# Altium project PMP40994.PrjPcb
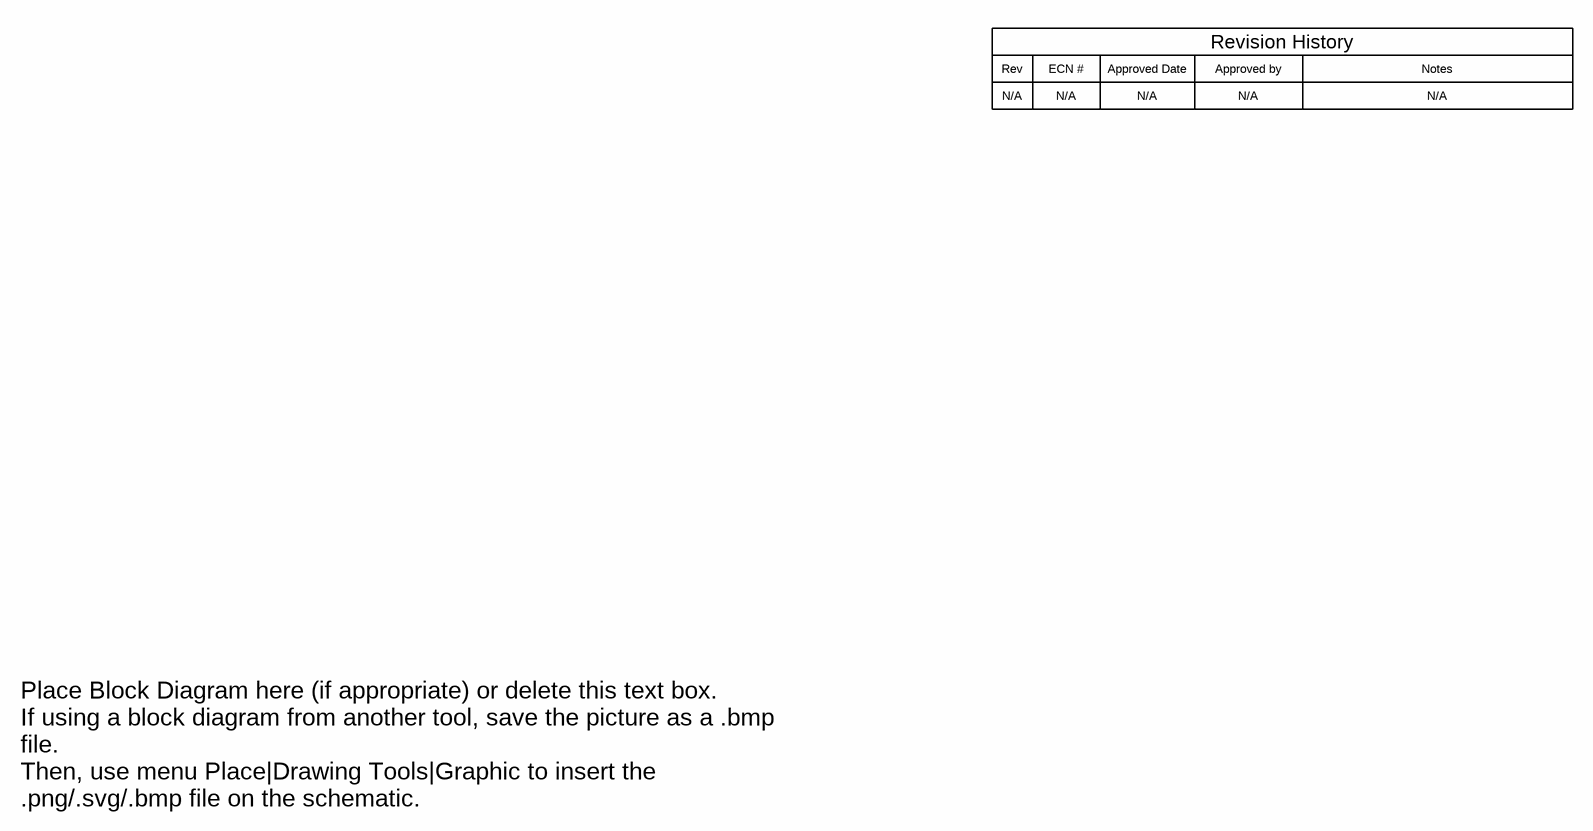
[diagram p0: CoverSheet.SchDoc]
CopyrightYear: 2022; EVM_Orderable: N/A; PCB_Layout: Max Wang; PCB_Rev: E1; PRJ_Customer: Public Release; PRJ_Engineer: Max Wang; PRJ_Number: PMP40994; PRJ_Title: Isolated Bias power and Gate Driver daughter board; SCH_Rev: E1; TechSupport: http://www.ti.com/support; TID: PMP40994
3 sheets, 65 parts. Net scope: global (net labels, ports and power ports of the same name join across sheets).
Board file: PMP40994.PcbDoc
Sheets:
  CoverSheet.SchDoc
  Driver Daughter board.SchDoc
  Hardware.SchDoc

## Sheet CoverSheet.SchDoc
size 431 x 279 mm; Date: Not shown in title block; ApprovedBy: Not shown in title block; CheckedBy: Not shown in title block; Author: Not shown in title block; CompanyName: Not shown in title block; Engineer: Not shown in title block; Organization: Not shown in title block; Address1: Not shown in title block; Address2: Not shown in title block; Address3: Not shown in title block; Address4: Not shown in title block; DocumentNumber: 1; Revision: Use project parameter SCH_Rev; SheetNumber: 1; SheetTotal: 3; PageSetup: Record=PageOptions¦CenterHorizontal=True¦CenterVertical=True¦PrintScale=1.00¦XCorrection=1.00¦YCorrection=1.00¦PrintKind=0¦BorderSize=5000000¦LeftOffset=0¦BottomOffset=0¦Orientation=2¦PaperLength=1000¦PaperWidth=1000¦Scale=100¦PaperSource=15¦PrintQuality=600¦MediaType=1¦DitherType=10¦PaperKind=Letter¦PrintScaleMode=1

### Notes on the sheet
- Rev
- N/A
- ECN #
- Approved Date
- Approved by
- Revision History
- Notes
- Place Block Diagram here (if appropriate) or delete this text box.
  If using a block diagram from another tool, save the picture as a .bmp file.
  Then, use menu Place|Drawing Tools|Graphic to insert the .png/.svg/.bmp file on the schematic.

## Sheet Driver Daughter board.SchDoc
size 431 x 279 mm; Date: Not shown in title block; ApprovedBy: Not shown in title block; CheckedBy: Not shown in title block; Author: Not shown in title block; CompanyName: Not shown in title block; Engineer: Not shown in title block; Organization: Not shown in title block; Address1: Not shown in title block; Address2: Not shown in title block; Address3: Not shown in title block; Address4: Not shown in title block; DocumentNumber: 1; Revision: Use project parameter SCH_Rev; SheetNumber: 1; SheetTotal: 3; PageSetup: Record=PageOptions¦CenterHorizontal=True¦CenterVertical=True¦PrintScale=1.00¦XCorrection=1.00¦YCorrection=1.00¦PrintKind=0¦BorderSize=5000000¦LeftOffset=0¦BottomOffset=0¦Orientation=2¦PaperLength=1000¦PaperWidth=1000¦Scale=100¦PaperSource=15¦PrintQuality=600¦MediaType=1¦DitherType=10¦PaperKind=Letter¦PrintScaleMode=1
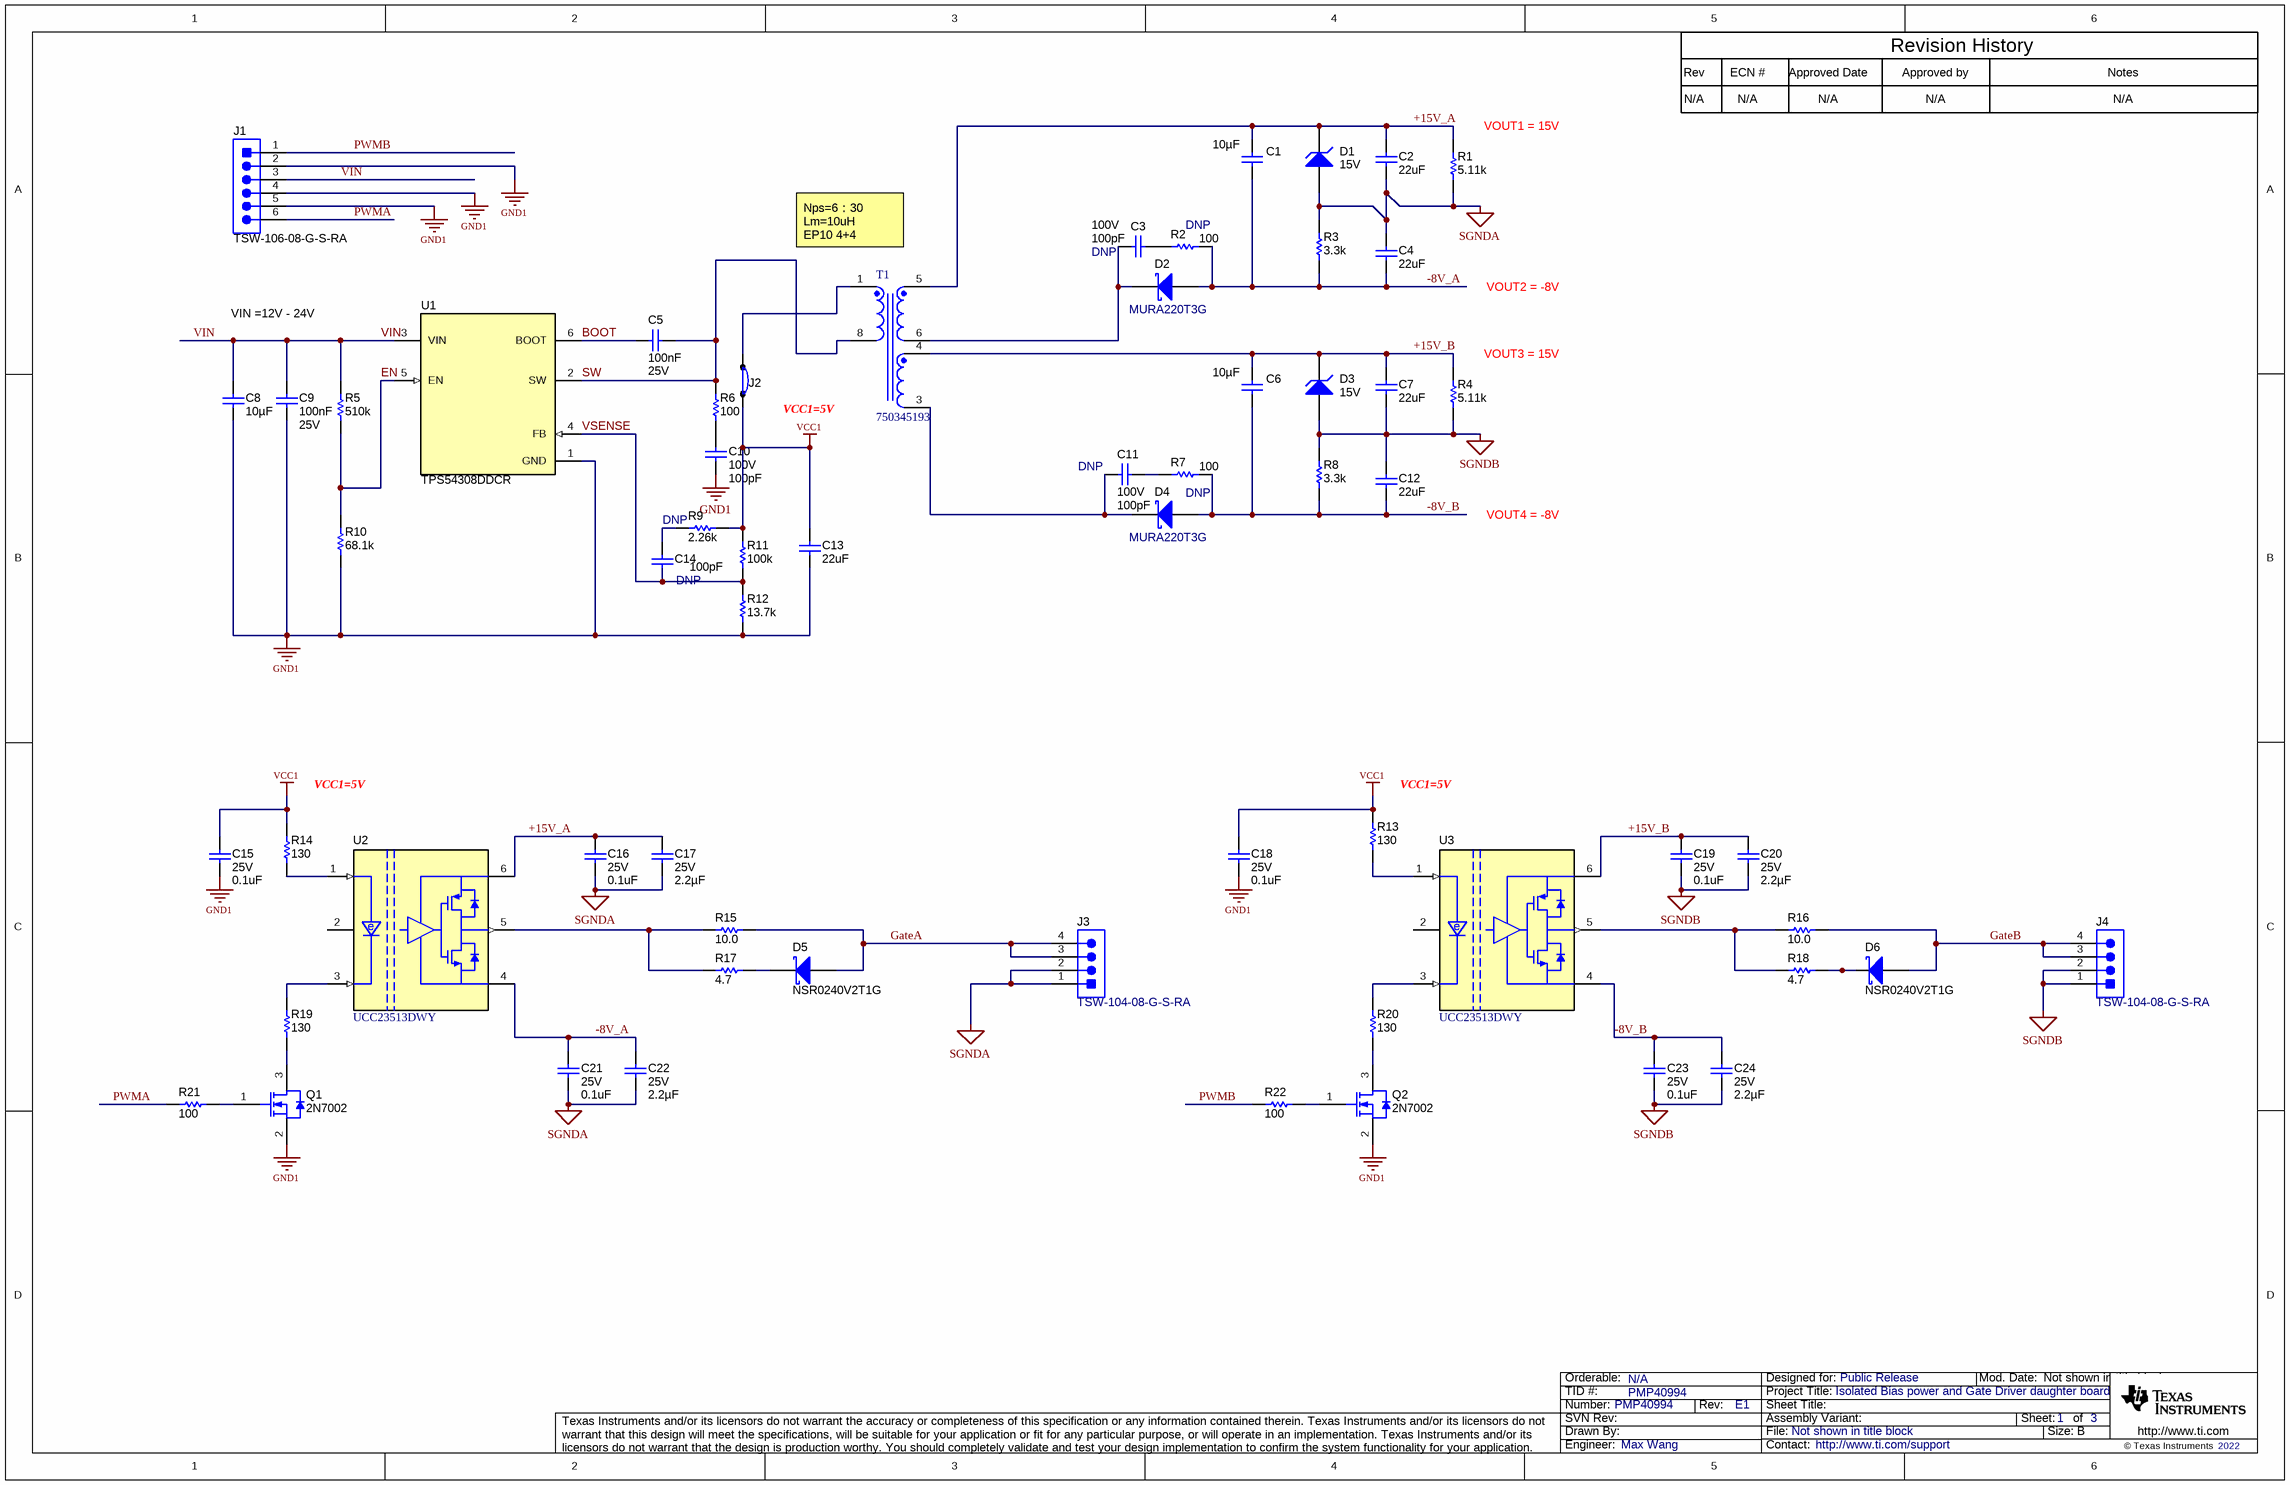
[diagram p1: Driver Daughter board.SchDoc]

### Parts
C1  ValueDisplayed: 10µF  [1210_280]  (hidden comment: C3225X7R1H106M250AC)
C2  ValueDisplayed: 22uF  [0805_HV]  (hidden comment: GRM21BR61C226ME44L)
C3  VDC_V: 100V  ValueDisplayed: 100pF  Parameter 1: DNP  [0603]  (hidden comment: GRM1885C2A101JA01D)
C4  ValueDisplayed: 22uF  [0805_HV]  (hidden comment: GRM21BR61C226ME44L)
C5  Cap_F: 100nF  VDC_V: 25V  [0603S]  (hidden comment: C1608X7R1E104K080AA)
C6  ValueDisplayed: 10µF  [1210_280]  (hidden comment: C3225X7R1H106M250AC)
C7  ValueDisplayed: 22uF  [0805_HV]  (hidden comment: GRM21BR61C226ME44L)
C8  ValueDisplayed: 10µF  [1210]  (hidden comment: GRM32ER7YA106KA12L)
C9  Cap_F: 100nF  VDC_V: 25V  [0603S]  (hidden comment: C1608X7R1E104K080AA)
C10  VDC_V: 100V  ValueDisplayed: 100pF  [0603S]  (hidden comment: GRM1885C2A101JA01D)
C11  VDC_V: 100V  ValueDisplayed: 100pF  Parameter 1: DNP  [0603]  (hidden comment: GRM1885C2A101JA01D)
C12  ValueDisplayed: 22uF  [0805_HV]  (hidden comment: GRM21BR61C226ME44L)
C13  ValueDisplayed: 22uF  [0805_HV]  (hidden comment: GRM21BR61C226ME44L)
C14  ValueDisplayed: 100pF  Parameter 1: DNP  [0603S]  (hidden comment: GRM1885C2A101JA01D)
C15  VDC_V: 25V  ValueDisplayed: 0.1uF  [0603S]  (hidden comment: C0603C104Z3VACTU)
C16  VDC_V: 25V  ValueDisplayed: 0.1uF  [0603S]  (hidden comment: C0603C104Z3VACTU)
C17  VDC_V: 25V  ValueDisplayed: 2.2µF  [0603S]  (hidden comment: GRM188C71E225KE11D)
C18  VDC_V: 25V  ValueDisplayed: 0.1uF  [0603S]  (hidden comment: C0603C104Z3VACTU)
C19  VDC_V: 25V  ValueDisplayed: 0.1uF  [0603S]  (hidden comment: C0603C104Z3VACTU)
C20  VDC_V: 25V  ValueDisplayed: 2.2µF  [0603S]  (hidden comment: GRM188C71E225KE11D)
C21  VDC_V: 25V  ValueDisplayed: 0.1uF  [0603S]  (hidden comment: C0603C104Z3VACTU)
C22  VDC_V: 25V  ValueDisplayed: 2.2µF  [0603S]  (hidden comment: GRM188C71E225KE11D)
C23  VDC_V: 25V  ValueDisplayed: 0.1uF  [0603S]  (hidden comment: C0603C104Z3VACTU)
C24  VDC_V: 25V  ValueDisplayed: 2.2µF  [0603S]  (hidden comment: GRM188C71E225KE11D)
D1  value 15V  [SOD-123]  (hidden comment: BZT52C15-7-F)
D2  PartNumber: MURA220T3G  [SMA]  (hidden comment: BYS12-90HE3_A/I)
D3  value 15V  [SOD-123]  (hidden comment: BZT52C15-7-F)
D4  PartNumber: MURA220T3G  [SMA]  (hidden comment: BYS12-90HE3_A/I)
D5  NSR0240V2T1G  [SOD-523]
D6  NSR0240V2T1G  [SOD-523]
J1  TSW-106-08-G-S-RA  [TSW-106-08-G-S-RA]
J2  ShortingJumper  [JMP-36-30X40SMT]  (value not drawn)
J3  TSW-104-08-G-S-RA  [TSW-104-08-G-S-RA]
J4  TSW-104-08-G-S-RA  [TSW-104-08-G-S-RA]
Q1  2N7002  [SOT-23]
Q2  2N7002  [SOT-23]
R1  ValueDisplayed: 5.11k  [0603S]  (hidden comment: CRCW06035K11FKEA)
R2  ValueDisplayed: 100  Parameter 1: DNP  [0805M]  (hidden comment: RT0805BRD07100RL)
R3  ValueDisplayed: 3.3k  [0603M]  (hidden comment: CRCW06033K30JNEA)
R4  ValueDisplayed: 5.11k  [0603S]  (hidden comment: CRCW06035K11FKEA)
R5  ValueDisplayed: 510k  [0603S]  (hidden comment: CRCW0603510KJNEA)
R6  ValueDisplayed: 100  [0603S]  (hidden comment: RC0603FR-07100RL)
R7  ValueDisplayed: 100  Parameter 1: DNP  [0805M]  (hidden comment: RT0805BRD07100RL)
R8  ValueDisplayed: 3.3k  [0603M]  (hidden comment: CRCW06033K30JNEA)
R9  ValueDisplayed: 2.26k  Parameter 1: DNP  [0603S]  (hidden comment: CRCW06032K26FKEA)
R10  ValueDisplayed: 68.1k  [0603S]  (hidden comment: CRCW060368K1FKEA)
R11  ValueDisplayed: 100k  [0603S]  (hidden comment: CRCW0603100KJNEA)
R12  ValueDisplayed: 13.7k  [0603S]  (hidden comment: CRCW060313K7FKEA)
R13  ValueDisplayed: 130  [0603S]  (hidden comment: CRCW0603130RJNEA)
R14  ValueDisplayed: 130  [0603S]  (hidden comment: CRCW0603130RJNEA)
R15  ValueDisplayed: 10.0  [2010]  (hidden comment: CRCW201010R0FKEF)
R16  ValueDisplayed: 10.0  [2010]  (hidden comment: CRCW201010R0FKEF)
R17  ValueDisplayed: 4.7  [2010]  (hidden comment: CRCW20104R70JNEF)
R18  ValueDisplayed: 4.7  [2010]  (hidden comment: CRCW20104R70JNEF)
R19  ValueDisplayed: 130  [0603S]  (hidden comment: CRCW0603130RJNEA)
R20  ValueDisplayed: 130  [0603S]  (hidden comment: CRCW0603130RJNEA)
R21  ValueDisplayed: 100  [0603S]  (hidden comment: CRCW0603100RJNEA)
R22  ValueDisplayed: 100  [0603S]  (hidden comment: CRCW0603100RJNEA)
T1  750345193  [750345193]
U1  TPS54308DDCR  [DDC0006A_N]
U2  UCC23513DWY  [DWY0006A]
U3  UCC23513DWY  [DWY0006A]

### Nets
GND1: C8.1 C9.2 C10.2 C13.1 C15.2 C18.2 J1.2 J1.4 J1.5 Q1.2(S) Q2.2(S) R10.1 R12.1 U1.1(GND)
SGNDA: C2.1 C4.2 C16.2 C17.2 C21.2 C22.2 D1.2(A) J3.1 J3.2 R1.1 R3.2
SGNDB: C7.1 C12.2 C19.2 C20.2 C23.2 C24.2 D3.2(A) J4.1 J4.2 R4.1 R8.2
VCC1: C13.2 C15.1 C18.1 J2.2 R9.2 R11.2 R13.2 R14.2
+15V_A: C1.1 C2.2 C16.1 C17.1 D1.1(K) R1.2 T1.5 U2.6(Vout)
+15V_B: C6.1 C7.2 C19.1 C20.1 D3.1(K) R4.2 T1.4 U3.6(Vout)
-8V_A: C1.2 C4.1 C21.1 C22.1 D2.2(A) R2.2 R3.1 U2.4(VSS)
-8V_B: C6.2 C12.1 C23.1 C24.1 D4.2(A) R7.2 R8.1 U3.4(VSS)
BOOT: C5.2 U1.6(BOOT)
EN: R5.1 R10.2 U1.5(EN)
GateA: D5.2(A) J3.3 J3.4 R15.2
GateB: D6.2(A) J4.3 J4.4 R16.2
PWMA: J1.6 R21.2
PWMB: J1.1 R22.2
SW: C5.1 R6.2 T1.8 U1.2(SW)
VIN: C8.2 C9.1 J1.3 R5.2 U1.3(VIN)
VSENSE: C14.2 R11.1 R12.2 U1.4(FB)
NetC3_1: C3.1 R2.1
NetC3_2: C3.2 D2.1(K) T1.6
NetC10_1: C10.1 R6.1
NetC11_1: C11.1 R7.1
NetC11_2: C11.2 D4.1(K) T1.3
NetC14_1: C14.1 R9.1
NetD5_1: D5.1(K) R17.2
NetD6_1: D6.1(K) R18.2
NetJ2_1: J2.1 T1.1
NetQ1_1: Q1.1(G) R21.1
NetQ1_3: Q1.3(D) R19.1
NetQ2_1: Q2.1(G) R22.1
NetQ2_3: Q2.3(D) R20.1
NetR13_1: R13.1 U3.1(Anode)
NetR14_1: R14.1 U2.1(Anode)
NetR15_1: R15.1 R17.1 U2.5(Vout)
NetR16_1: R16.1 R18.1 U3.5(Vout)
NetR19_2: R19.2 U2.3(Cathode)
NetR20_2: R20.2 U3.3(Cathode)

Not connected (* = marked no-connect by the designer): U2 2(NC); U3 2(NC)

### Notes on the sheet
- Rev
- N/A
- ECN #
- Approved Date
- Approved by
- Revision History
- Notes
- (near R1) VOUT1 = 15V
- (near T1) Nps=6：30
  Lm=10uH
  EP10 4+4
- VOUT2 = -8V
- VIN =12V - 24V
- (near R4) VOUT3 = 15V
- VCC1=5V
- VOUT4 = -8V
- (near R14) VCC1=5V
- (near R13) VCC1=5V

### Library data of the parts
C1 C6 = C3225X7R1H106M250AC: CAP, CERM, 10 µF, 50 V, +/- 20%, X7R, 1210; Manufacturer: TDK; Polarized: N; CompType: Capacitor; Value: 10uF; U/M: EA; Cap_F: 0.00001; Tolerance_%: 20; Value1: Unknown; VDC_V: 50; Value2: 50V; TaMin_C: -55; TaMax_C: 125; Cap_Case: 1210; SizeArea_mm2: 8; SizeAreaWB_mm2: 14.7; SizeX_mm: 3.2; SizeY_mm: 2.5; SizeZ_mm: 2.8; AEC Category: Q200
C2 C4 C7 C12 C13 = CMP-0008294-2: CAP, CERM, 22 uF, 16 V, +/- 20%, X5R, 0805; Manufacturer: MuRata; TaMin_C: -55°C; Polarized: N; SizeAreaWB_mm2: 6.75; Value1: Unknown; U/M: EA; Value: 22uF; TaMax_C: 85°C; SizeZ_mm: 1.45; SizeX_mm: 2; SizeY_mm: 1.25; Cap_Case: 0805; Value2: 16V; SizeArea_mm2: 2.5; CompType: Capacitor; Cap_F: 22µF; AEC Category: Q200
C3 C11 = CMP-0007237-3: CAP, CERM, 100 pF, 100 V, +/- 5%, C0G/NP0, 0603; Manufacturer: MuRata; TaMin_C: -55°C; Polarized: N; SizeAreaWB_mm2: 4.68; Value1: Unknown; U/M: EA; Value: 100pF; TaMax_C: 125°C; SizeZ_mm: 1; SizeX_mm: 1.6; SizeY_mm: 0.8; SizeArea_mm2: 1.28; AEC Category: Q200
C5 C9 = CMP-0007039-5: CAP, CERM, 0.1 uF, 25 V, +/- 10%, X7R, 0603; Manufacturer: TDK; TaMin_C: -55°C; Polarized: N; SizeAreaWB_mm2: 4.68; Value1: Unknown; U/M: EA; Value: 0.1uF; TaMax_C: 125°C; SizeZ_mm: 1; SizeX_mm: 1.6; SizeY_mm: 0.8; Cap_Case: 0603; SizeArea_mm2: 1.28; AEC Category: Q200
C8 = GRM32ER7YA106KA12L: CAP, CERM, 10 µF, 35 V, +/- 10%, X7R, 1210; Manufacturer: MuRata; Polarized: N; CompType: Capacitor; Value: 10uF; U/M: EA; Cap_F: 0.00001; Tolerance_%: 10; Value1: Unknown; VDC_V: 35; Value2: 35V; TaMin_C: -55; TaMax_C: 125; SizeArea_mm2: 8; SizeAreaWB_mm2: 14.7; SizeX_mm: 3.2; SizeY_mm: 2.5; SizeZ_mm: 2.7; AEC Category: Q200
C10 = CMP-0007237-3: CAP, CERM, 100 pF, 100 V, +/- 5%, C0G/NP0, 0603; Manufacturer: MuRata; TaMin_C: -55°C; Polarized: N; SizeAreaWB_mm2: 4.68; Value1: Unknown; U/M: EA; Value: 100pF; TaMax_C: 125°C; SizeZ_mm: 1; SizeX_mm: 1.6; SizeY_mm: 0.8; Cap_Case: 0603; SizeArea_mm2: 1.28; AEC Category: Q200
C14 = CMP-0007237-3: CAP, CERM, 100 pF, 100 V, +/- 5%, C0G/NP0, 0603; Manufacturer: MuRata; TaMin_C: -55°C; Polarized: N; SizeAreaWB_mm2: 4.68; Value1: Unknown; U/M: EA; Value: 100pF; TaMax_C: 125°C; SizeZ_mm: 1; SizeX_mm: 1.6; SizeY_mm: 0.8; Cap_Case: 0603; Value2: 100V; SizeArea_mm2: 1.28; AEC Category: Q200
C15 C16 C18 C19 C21 C23 = CMP-0006865-1: CAP, CERM, 0.1 uF, 25 V, +80/-20%, Y5V, 0603; Manufacturer: Kemet; TaMin_C: -30°C; Polarized: N; SizeAreaWB_mm2: 4.68; Value1: Unknown; U/M: EA; Value: 0.1uF; TaMax_C: 85°C; Tolerance_%: 80%; SizeZ_mm: 1; SizeX_mm: 1.6; SizeY_mm: 0.8; Cap_Case: 0603; SizeArea_mm2: 1.28; Cap_F: 100nF; AEC Category: Q200
C17 C20 C22 C24 = CMP-0075366-2: CAP, CERM, 2.2 µF, 25 V,+/- 10%, X7S, 0603; Manufacturer: MuRata; TaMin_C: -55°C; Polarized: N; SizeAreaWB_mm2: 4.68; U/M: EA; Value: 2.2uF; TaMax_C: 125°C; SizeZ_mm: 1.0; SizeX_mm: 1.6; SizeY_mm: 0.8; Cap_Case: 0603; SizeArea_mm2: 1.28; AEC Category: Q200
D1 D3 = BZT52C15-7-F: Diode, Zener, 15 V, 370 mW, AEC-Q101, SOD-123; Manufacturer: Diodes Inc.; SymbolCreator: a0412235; U/M: EA; Power_W: 0.37; Vz_V: 15; Value1: 0.37W; RJA_CperW: 338; AEC Category: Q101; AEC Qualified: Y
D2 D4 = CMP-0028924-2: Diode, Schottky, 200 V,  2A, , SMA; Manufacturer: Onsemi; SizeY_mm: 2.92; AEC Qualified: Y; Io_A: 1A; TJmax_C: 150°C; SizeZ_mm: 2.87; Vr_V: 90V; SizeX_mm: 5.59; Value2: 0.75V; SizeAreaWB_mm2: 37.3428; Value: 200V; Green_Lifecycle: Not Set; AEC Category: Q101; Vf_V: 750mV; Green_REACh: Incomplete; SizeArea_mm2: 16.3228
D5 D6 = NSR0240V2T1G: Diode, Schottky, 40 V, 0.25 A, SOD-523; Manufacturer: ON Semiconductor; U/M: EA; Vf_V: 0.7; Value: 40V; Value1: 0.25A; Value2: 0.7V; Io_A: 0.25; Vr_V: 40; TJmax_C: 150; SizeAreaWB_mm2: 5.13; SizeArea_mm2: 1.53; SizeX_mm: 1.7; SizeY_mm: 0.9; SizeZ_mm: 0.65; AEC Category: Q101; Green_Lifecycle: Active; Green_REACh: Passed
J1 = TSW-106-08-G-S-RA: Header, 100mil, 6x1, Gold, R/A, TH; Manufacturer: Samtec; SymbolCreator: a0412235; Pitch_mm: 2.54; Gender: Male; Shrouded: N; Row_Count: 1; Current_A: 6.3; Voltage_V: 550; Cert_CSA: Y; Green_Lifecycle: Active; Green_REACh: Passed
J2 = CMP-0003883-1: Jumper, SMT; Manufacturer: Any
J3 J4 = CMP-0055978-1: Header, 100mil, 4x1, Gold, R/A, TH; Manufacturer: Samtec; Cert_VDE: N; CNHeader: FALSE; Current_A: 6.3A; Green_Lifecycle: Active; Gender: Male; Cert_CSA: Y; Green_REACh: Passed; Voltage_V: 550V; Row_Count: 1; Pitch_mm: 2.54
Q1 Q2 = 2N7002: MOSFET, N-CH, 60 V, 115 A, SOT-23; Manufacturer: Fairchild Semiconductor; Alternate Manufacturer: None; U/M: EA; ChType: N; Value: 60V; VdsMax_V: 60; Value1: ? ohm; Value2: ? nC; Vgs_V: 20; IdsMax_A: 115; SizeAreaWB_mm2: 14; SizeArea_mm2: 7.5; SizeX_mm: 2.5; SizeY_mm: 3; SizeZ_mm: 1.1; AEC Category: Q101
R1 R4 = CMP-0022509-2: RES, 5.11 k, 1%, 0.1 W, 0603; Manufacturer: Vishay-Dale; Power_W: 100mW; TempCo: 100 ppm/C; Value_Code: 5k11; U/M: EA; Value: 5.11k; EIA_Code: E96; SizeX_mm: 1.6; SizeY_mm: 0.8; SizeZ_mm: 1; Value2: 0.1W; SizeArea_mm2: 1.28; VDC_V: 75V; AEC Category: Q200
R2 R7 = RT0805BRD07100RL: RES, 100, 0.1%, 0.125 W, 0805; Manufacturer: Yageo America; CompType: Resistor; Value: 100; Value_Code: 100R; Tolerance_%: 0.1; Power_W: 0.125; Value2: 0.125W; VDC_V: 150; TempCo: 25 ppm/C; SizeArea_mm2: 2.5; SizeX_mm: 2; SizeY_mm: 1.25; SizeZ_mm: 1.45; EIA_Code: E192; U/M: EA; AEC Category: Q200; Green_Lifecycle: Active; Green_REACh: Passed
R3 R8 = CRCW06033K30JNEA: RES, 3.3 k, 5%, 0.1 W, 0603; Manufacturer: Vishay-Dale; CompType: Resistor; Value: 3.3k; Res_ohm: 3300; Value_Code: 3k30; Tolerance_%: 5; Power_W: 0.1; Value2: 0.1W; VDC_V: 75; TempCo: 200 ppm/C; SizeArea_mm2: 1.28; SizeX_mm: 1.6; SizeY_mm: 0.8; SizeZ_mm: 1; EIA_Code: E24; U/M: EA; AEC Category: Q200; Green_Lifecycle: Active; Green_REACh: Passed
R5 = CMP-0025822-1: RES, 510 k, 5%, 0.1 W, 0603; Manufacturer: Vishay-Dale; Power_W: 100mW; TempCo: 200 ppm/C; U/M: EA; Value: 510k; EIA_Code: E24; SizeX_mm: 1.6; SizeY_mm: 0.8; SizeZ_mm: 1; Value2: 0.1W; SizeArea_mm2: 1.28; VDC_V: 75V; AEC Category: Q200
R6 = CMP-0022736-4: RES, 100, 1%, 0.1 W, 0603; Manufacturer: Yageo; Power_W: 100mW; TempCo: 100 ppm/C; Value_Code: 100R; Value: 100; EIA_Code: E96; SizeX_mm: 1.6; SizeY_mm: 0.8; SizeZ_mm: 1; Value2: 0.1W; SizeArea_mm2: 1.28; AEC Qualified: N; VDC_V: 75V; AEC Category: Q200; SizeAreaWB_mm2: 4.68
R9 = CMP-0022273-3: RES, 2.26 k, 1%, 0.1 W, 0603; Manufacturer: Vishay-Dale; Power_W: 100mW; TempCo: 100 ppm/C; Value_Code: 2k26; U/M: EA; Value: 2.26k; EIA_Code: E96; SizeX_mm: 1.6; SizeY_mm: 0.8; SizeZ_mm: 1; Value2: 0.1W; SizeArea_mm2: 1.28; VDC_V: 75V; AEC Category: Q200
R10 = CMP-0022552-3: RES, 68.1 k, 1%, 0.1 W, 0603; Manufacturer: Vishay-Dale; Power_W: 100mW; TempCo: 100 ppm/C; Value_Code: 68k1; U/M: EA; Value: 68.1k; EIA_Code: E96; SizeX_mm: 1.6; SizeY_mm: 0.8; SizeZ_mm: 1; Value2: 0.1W; SizeArea_mm2: 1.28; VDC_V: 75V; AEC Category: Q200
R11 = CMP-0025698-1: RES, 100 k, 5%, 0.1 W, 0603; Manufacturer: Vishay-Dale; Power_W: 100mW; TempCo: 200 ppm/C; U/M: EA; Value: 100k; EIA_Code: E24; SizeX_mm: 1.6; SizeY_mm: 0.8; SizeZ_mm: 1; Value2: 0.1W; SizeArea_mm2: 1.28; VDC_V: 75V; AEC Category: Q200
R12 = CMP-0022044-1: RES, 13.7 k, 1%, 0.1 W, 0603; Manufacturer: Vishay-Dale; Power_W: 100mW; TempCo: 100 ppm/C; Value_Code: 13k7; U/M: EA; Value: 13.7k; EIA_Code: E96; SizeX_mm: 1.6; SizeY_mm: 0.8; SizeZ_mm: 1; Value2: 0.1W; SizeArea_mm2: 1.28; VDC_V: 75V; AEC Category: Q200
R13 R14 R19 R20 = CMP-0025714-1: RES, 130, 5%, 0.1 W, 0603; Manufacturer: Vishay-Dale; Power_W: 100mW; TempCo: 200 ppm/C; Value_Code: 130R; U/M: EA; Value: 130; EIA_Code: E24; SizeX_mm: 1.6; SizeY_mm: 0.8; SizeZ_mm: 1; Value2: 0.1W; SizeArea_mm2: 1.28; VDC_V: 75V; AEC Category: Q200
R15 R16 = CRCW201010R0FKEF: RES, 10.0, 1%, 0.75 W, AEC-Q200 Grade 0, 2010; Manufacturer: Vishay-Dale; CompType: Resistor; Value: 10.0; Res_ohm: 10; Value_Code: 10R0; Tolerance_%: 1; Power_W: 0.75; Value2: 0.75W; VDC_V: 400; TempCo: 100 ppm/C; SizeArea_mm2: 12.5; SizeX_mm: 5; SizeY_mm: 2.5; SizeZ_mm: 1.66; EIA_Code: E96; U/M: EA; AEC Category: Q200; AEC Qualified: Y; AEC Grade: 0
R17 R18 = CRCW20104R70JNEF: RES, 4.7, 5%, 0.75 W, AEC-Q200 Grade 0, 2010; Manufacturer: Vishay-Dale; CompType: Resistor; Value: 4.7; Value_Code: 4R70; Tolerance_%: 5; Power_W: 0.75; Value2: 0.75W; VDC_V: 400; TempCo: 200 ppm/C; SizeArea_mm2: 12.5; SizeY_mm: 2.5; SizeZ_mm: 1.66; EIA_Code: E24; U/M: EA; AEC Category: Q200; AEC Qualified: Y; AEC Grade: 0
R21 R22 = CRCW0603100RJNEA: RES, 100, 5%, 0.1 W, 0603; Manufacturer: Vishay-Dale; CompType: Resistor; Value: 100; Value_Code: 100R; Tolerance_%: 5; Power_W: 0.1; Value2: 0.1W; VDC_V: 75; TempCo: 200 ppm/C; SizeArea_mm2: 1.28; SizeX_mm: 1.6; SizeY_mm: 0.8; SizeZ_mm: 1; EIA_Code: E24; U/M: EA; AEC Category: Q200
T1 = 750345193: 10uH EP10 Wurth
U1 = CMP-0013278-3: 4.5-V to 28-V Input, 3-A Output Synchronous Step-Down Converter, DDC0006A (SOT-6); Alternate PartNumber: TPS54308DDCT; Manufacturer: Texas Instruments; SizeZ_mm: 0.87; SizeX_mm: 1.65; SizeY_mm: 2.95; SizeArea_mm2: 4.8675; CompType: IC; U/M: EA; SizeAreaWB_mm2: 10.4675
U2 U3 = CMP-0081091-2: 5-kVRMS, 3-A Single Channel Isolated Gate Driver with Opto Compatible Input, DWY0006A (SOIC-6); Alternate PartNumber: UCC23513DWYR; Alternate Manufacturer: Texas Instruments; SizeAreaWB_mm2: 90.18; SizeZ_mm: 3.43; SizeX_mm: 11.5; SizeY_mm: 4.68; SizeArea_mm2: 53.82; CompType: IC; AEC Qualified: N; AEC Category: Q200

## Sheet Hardware.SchDoc
size 431 x 279 mm; Date: Not shown in title block; ApprovedBy: Not shown in title block; CheckedBy: Not shown in title block; Author: Not shown in title block; CompanyName: Not shown in title block; Engineer: Not shown in title block; Organization: Not shown in title block; Address1: Not shown in title block; Address2: Not shown in title block; Address3: Not shown in title block; Address4: Not shown in title block; DocumentNumber: 3; Revision: Use project parameter SCH_Rev; SheetNumber: 3; SheetTotal: 3; PageSetup: Record=PageOptions¦CenterHorizontal=True¦CenterVertical=True¦PrintScale=1.00¦XCorrection=1.00¦YCorrection=1.00¦PrintKind=0¦BorderSize=5000000¦LeftOffset=0¦BottomOffset=0¦Orientation=2¦PaperLength=1000¦PaperWidth=1000¦Scale=100¦PaperSource=15¦PrintQuality=600¦MediaType=1¦DitherType=10¦PaperKind=Letter¦PrintScaleMode=1
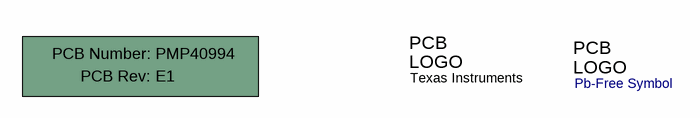
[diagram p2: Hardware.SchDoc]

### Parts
Logo1  Texas Instruments  [TI_Symbol_Overlay_Small]  (no BOM)
Logo2  Pb-Free Symbol  [Pb-Free_Overlay_Small]  (no BOM)
PCB1  Printed Circuit Board  (value not drawn)  (mechanical)

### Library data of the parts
Logo1 = CMP-0074838-1: Texas Instrument Corporate Signature; SymbolCreator: a0412235; Lib Reference: TI_Logo; Library Reference: Logo
Logo2 = CMP-0074839-1: SymbolCreator: a0412235
PCB1 = CMP-0003618-2: Manufacturer: Any; PartNumber: PMP40994

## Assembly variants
001: all parts fitted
